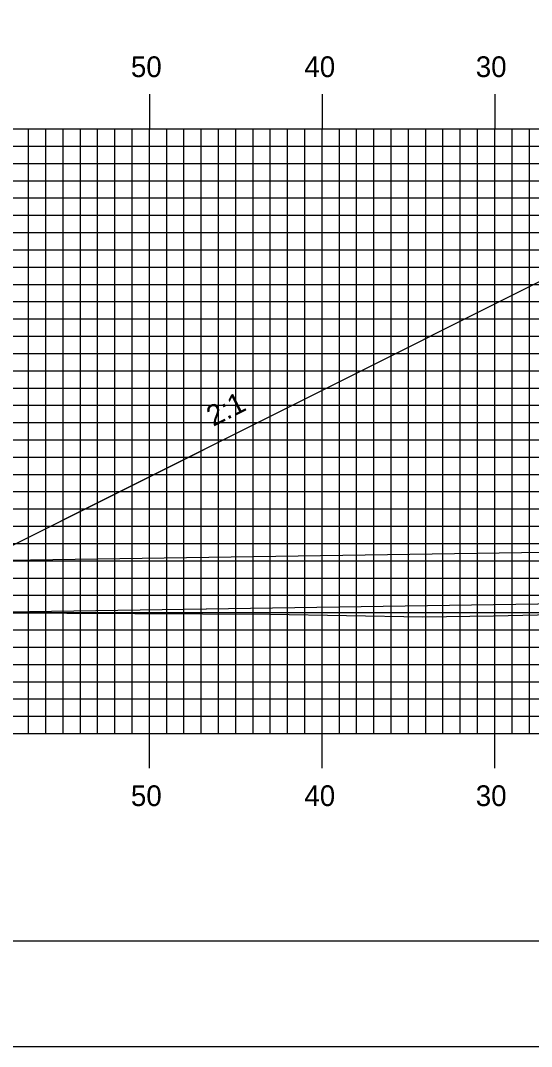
# Model space of a CAD drawing. Extents: x 1789730 to 1790074, y 442591 to 442811.
# Drawn here: x 1789838.7 to 1789868.3, y 442590.5 to 442649.9 of the extents above; entities that cross this region are included whole.
import ezdxf

# ---------------------------------------------------------------- set-up
doc = ezdxf.new("R2010")
doc.units = 0
for name, color, linetype in [('ANNOTATION', 7, 'Continuous'), ('BORDER', 7, 'Continuous'), ('D_Drainage_Culvert', 7, 'Continuous'), ('D_Roadway_Centerline', 7, 'Continuous'), ('D_Roadway_SlopeLines', 7, 'Continuous'), ('H_V ANNOTATION', 7, 'Continuous'), ('MAJOR', 7, 'Continuous'), ('MINOR', 7, 'Continuous'), ('PLOT BOUNDARY', 7, 'Continuous'), ('S_Roadway_Centerline', 7, 'Continuous')]:
    doc.layers.add(name, color=color, linetype=linetype)

msp = doc.modelspace()

# ---------------------------------------------------------------- linework, layer by layer
at = {"layer": 'BORDER'}
msp.add_lwpolyline([(1789746.583, 442596.665), (1790066.583, 442596.665), (1790066.583, 442806.665), (1789746.583, 442806.665)], close=True, dxfattribs=at)
at = {"layer": 'D_Drainage_Culvert'}
msp.add_lwpolyline([(1789830.264, 442615.576), (1789830.219, 442618.576), (1789958.204, 442620.494), (1789958.249, 442617.494)], close=True, dxfattribs=at)
at = {"layer": 'D_Roadway_Centerline'}
msp.add_lwpolyline([(1789830.28, 442615.576), (1789868.433, 442634.652), (1789873.183, 442637.027), (1789876.183, 442637.147), (1789884.183, 442637.467), (1789896.183, 442637.707), (1789908.183, 442637.467), (1789916.183, 442637.147), (1789919.183, 442637.027), (1789923.933, 442634.652), (1789958.249, 442617.494)], dxfattribs=at)
at = {"layer": 'D_Roadway_SlopeLines'}
msp.add_lwpolyline([(1789873.183, 442637.027), (1789830.28, 442615.576)], dxfattribs=at)
at = {"layer": 'MAJOR'}
for p, q in [((1789846.183, 442645.669), (1789846.183, 442643.665)), ((1789856.183, 442645.669), (1789856.183, 442643.665)), ((1789866.183, 442645.669), (1789866.183, 442643.665)), ((1789756.183, 442643.665), (1790036.183, 442643.665)), ((1789756.183, 442643.665), (1790036.183, 442643.665)), ((1789846.183, 442608.665), (1789846.183, 442643.665)), ((1789856.183, 442608.665), (1789856.183, 442643.665)), ((1789866.183, 442608.665), (1789866.183, 442643.665)), ((1789756.183, 442638.665), (1790036.183, 442638.665)), ((1789756.183, 442633.665), (1790036.183, 442633.665)), ((1789756.183, 442628.665), (1790036.183, 442628.665)), ((1789756.183, 442623.665), (1790036.183, 442623.665)), ((1789756.183, 442618.665), (1790036.183, 442618.665)), ((1789756.183, 442613.665), (1790036.183, 442613.665)), ((1789756.183, 442608.665), (1790036.183, 442608.665)), ((1789756.183, 442608.665), (1790036.183, 442608.665)), ((1789846.183, 442606.661), (1789846.183, 442608.665)), ((1789856.183, 442606.661), (1789856.183, 442608.665)), ((1789866.183, 442606.661), (1789866.183, 442608.665))]:
    msp.add_line(p, q, dxfattribs=at)
at = {"layer": 'MINOR'}
for p, q in [((1789839.183, 442608.665), (1789839.183, 442643.665)), ((1789840.183, 442608.665), (1789840.183, 442643.665)), ((1789841.183, 442608.665), (1789841.183, 442643.665)), ((1789842.183, 442608.665), (1789842.183, 442643.665)), ((1789843.183, 442608.665), (1789843.183, 442643.665)), ((1789844.183, 442608.665), (1789844.183, 442643.665)), ((1789845.183, 442608.665), (1789845.183, 442643.665)), ((1789847.183, 442608.665), (1789847.183, 442643.665)), ((1789848.183, 442608.665), (1789848.183, 442643.665)), ((1789849.183, 442608.665), (1789849.183, 442643.665)), ((1789850.183, 442608.665), (1789850.183, 442643.665)), ((1789851.183, 442608.665), (1789851.183, 442643.665)), ((1789852.183, 442608.665), (1789852.183, 442643.665)), ((1789853.183, 442608.665), (1789853.183, 442643.665)), ((1789854.183, 442608.665), (1789854.183, 442643.665)), ((1789855.183, 442608.665), (1789855.183, 442643.665)), ((1789857.183, 442608.665), (1789857.183, 442643.665)), ((1789858.183, 442608.665), (1789858.183, 442643.665)), ((1789859.183, 442608.665), (1789859.183, 442643.665)), ((1789860.183, 442608.665), (1789860.183, 442643.665)), ((1789861.183, 442608.665), (1789861.183, 442643.665)), ((1789862.183, 442608.665), (1789862.183, 442643.665)), ((1789863.183, 442608.665), (1789863.183, 442643.665)), ((1789864.183, 442608.665), (1789864.183, 442643.665)), ((1789865.183, 442608.665), (1789865.183, 442643.665)), ((1789867.183, 442608.665), (1789867.183, 442643.665)), ((1789868.183, 442608.665), (1789868.183, 442643.665)), ((1789756.183, 442642.665), (1790036.183, 442642.665)), ((1789756.183, 442641.665), (1790036.183, 442641.665)), ((1789756.183, 442640.665), (1790036.183, 442640.665)), ((1789756.183, 442639.665), (1790036.183, 442639.665)), ((1789756.183, 442637.665), (1790036.183, 442637.665)), ((1789756.183, 442636.665), (1790036.183, 442636.665)), ((1789756.183, 442635.665), (1790036.183, 442635.665)), ((1789756.183, 442634.665), (1790036.183, 442634.665)), ((1789756.183, 442632.665), (1790036.183, 442632.665)), ((1789756.183, 442631.665), (1790036.183, 442631.665)), ((1789756.183, 442630.665), (1790036.183, 442630.665)), ((1789756.183, 442629.665), (1790036.183, 442629.665)), ((1789756.183, 442627.665), (1790036.183, 442627.665)), ((1789756.183, 442626.665), (1790036.183, 442626.665)), ((1789756.183, 442625.665), (1790036.183, 442625.665)), ((1789756.183, 442624.665), (1790036.183, 442624.665)), ((1789756.183, 442622.665), (1790036.183, 442622.665)), ((1789756.183, 442621.665), (1790036.183, 442621.665)), ((1789756.183, 442620.665), (1790036.183, 442620.665)), ((1789756.183, 442619.665), (1790036.183, 442619.665)), ((1789756.183, 442617.665), (1790036.183, 442617.665)), ((1789756.183, 442616.665), (1790036.183, 442616.665)), ((1789756.183, 442615.665), (1790036.183, 442615.665)), ((1789756.183, 442614.665), (1790036.183, 442614.665)), ((1789756.183, 442612.665), (1790036.183, 442612.665)), ((1789756.183, 442611.665), (1790036.183, 442611.665)), ((1789756.183, 442610.665), (1790036.183, 442610.665)), ((1789756.183, 442609.665), (1790036.183, 442609.665))]:
    msp.add_line(p, q, dxfattribs=at)
at = {"layer": 'PLOT BOUNDARY'}
msp.add_lwpolyline([(1789730.396, 442590.547), (1790070.396, 442590.547), (1790070.396, 442810.547), (1789730.396, 442810.547)], close=True, dxfattribs=at)
at = {"layer": 'S_Roadway_Centerline'}
msp.add_lwpolyline([(1789756.183, 442614.574), (1789756.955, 442614.58), (1789763.548, 442614.532), (1789775.198, 442615.036), (1789775.617, 442615.038), (1789775.999, 442615.03), (1789793.851, 442614.254), (1789805.867, 442614.466), (1789810.51, 442614.559), (1789816.559, 442614.833), (1789824.936, 442615.213), (1789829.984, 442615.573), (1789837.454, 442615.651), (1789853.174, 442615.574), (1789862.008, 442615.419), (1789866.101, 442615.468), (1789877.117, 442615.721)], dxfattribs=at)

# ---------------------------------------------------------------- texts
at = {"layer": 'ANNOTATION'}
msp.add_text('2:1', height=1.2, rotation=26.56505, dxfattribs=at).set_placement((1789849.877, 442626.411))
at = {"layer": 'H_V ANNOTATION'}
for s, p in [('50', (1789845.112, 442646.665)), ('40', (1789855.155, 442646.665)), ('30', (1789865.08, 442646.665)), ('50', (1789845.112, 442604.465)), ('40', (1789855.155, 442604.465)), ('30', (1789865.08, 442604.465))]:
    msp.add_text(s, height=1.2, dxfattribs=at).set_placement(p)

doc.saveas('drawing.dxf')
